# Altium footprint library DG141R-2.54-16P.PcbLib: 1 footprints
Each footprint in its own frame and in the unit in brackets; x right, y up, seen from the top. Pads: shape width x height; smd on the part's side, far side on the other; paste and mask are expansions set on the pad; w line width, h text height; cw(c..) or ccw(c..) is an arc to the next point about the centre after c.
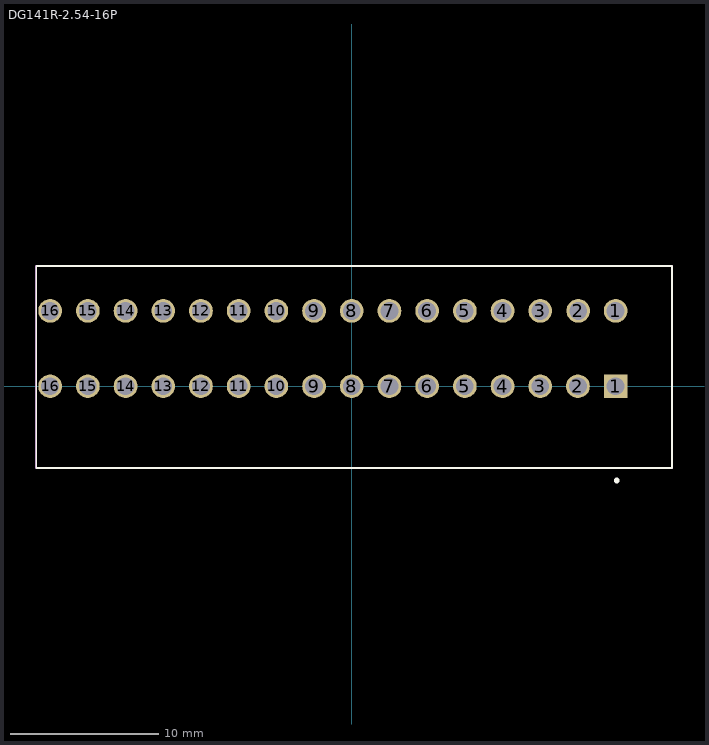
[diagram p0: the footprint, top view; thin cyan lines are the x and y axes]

## DG141R-2.54-16P [mm]
pads (32):
  rect 1.6x1.6 hole 1.2: 1(17.78,0)
  round 1.6 hole 1.2: 1(17.78,5.08) 2(15.24,0) 2(15.26,5.08) 3(12.7,0) 3(12.7,5.08) 4(10.16,0) 4(10.16,5.08) 5(7.62,0) 5(7.62,5.08) 6(5.08,0) 6(5.08,5.08) 7(2.54,0) 7(2.54,5.08) 8(0,0) 8(0,5.08) 9(-2.54,0) 9(-2.54,5.08) 10(-5.08,0) 10(-5.08,5.08) 11(-7.62,0) 11(-7.62,5.08) 12(-10.16,0) 12(-10.16,5.08) 13(-12.7,0) 13(-12.7,5.08) 14(-15.24,0) 14(-15.24,5.08) 15(-17.78,0) 15(-17.78,5.08) 16(-20.32,0) 16(-20.32,5.08)
Top Overlay:
  circle w0.2: c17.856,-6.35 r0.1
  lines w0.127: -21.26,-5.5 -21.26,8.1 21.59,8.1 21.59,-5.5 -21.26,-5.5
Mechanical 13:
  lines w0.127: -21.285,-5.5 -21.285,8.1 21.59,8.1 21.59,-5.5 -21.285,-5.5
3D body "DG141R-2.54-16P.stp": height 12.6, standoff -3.2, extent -21.286,-5.577 21.894,8.023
